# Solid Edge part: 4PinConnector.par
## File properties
Author: conerly
Template: Normal.par
Last saved by: jccrumbl
Revision: 55
Application: Solid Edge
Density: 1024.000 kg/m^3
Accuracy: 0.990
Material: ABS Plastic, high impact
Face Style: Red
Fill Style: ANSI34(Plastic)
Virtual Style: Red (Shiny)
Coef. of Thermal Exp: 9e-05
Thermal Conductivity: 0.2
Specific Heat: 0.0
Modulus of Elasticity: 1378951400.0
Poisson's Ratio: 0.4
Yield Stress: 31026406.5
Ultimate Stress: 0.0
Elongation: 0.0
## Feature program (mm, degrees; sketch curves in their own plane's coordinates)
sketch for "unnamed Protrusion 1" plane through (0, 0, 0) normal (0, 0, 1) x-axis (1, 0, 0)
  line (-37.2884, 10.9984) -> (-27.5384, 10.9984)
  line (-27.5384, 10.9984) -> (-27.5384, 20.7484)
  line (-27.5384, 20.7484) -> (-37.2884, 20.7484)
  line (-37.2884, 20.7484) -> (-37.2884, 10.9984)
  dimension (linear) = 27.5384
  dimension (linear) = 37.2884
extrude "unnamed Protrusion 1" add finite 25 along +normal
sketch for "ExtrudedProtrusion_3" plane through (-32.5384, 13.9984, 12.5) normal (0, -1, 0) x-axis (0, 0, 1)
  line (12.5, 4.75) -> (9.2, 4.75)
  line (9.2, 4.75) -> (9.2, 6.25)
  line (9.2, 6.25) -> (12.5, 4.75)
extrude "ExtrudedProtrusion_3" add finite 3.5 along -normal
sketch for "ExtrudedProtrusion_4" #1 plane through (-32.5384, 17.4984, 0) normal (0, 0, -1) x-axis (0, 1, 0)
  line (4.25, -3.75) -> (4.25, -5.75)
  line (4.25, -5.75) -> (2.25, -5.75)
  line (2.25, -3.75) -> (2.25, -5.75)
  line (4.25, -3.75) -> (2.25, -3.75)
sketch for "ExtrudedProtrusion_4" #2 plane through (-32.5384, 17.4984, 0) normal (0, 0, -1) x-axis (0, 1, 0)
  line (-5.5, -5.5) -> (-7.5, -5.5)
  line (-7.5, -5.5) -> (-7.5, -3.5)
  line (-5.5, -3.5) -> (-7.5, -3.5)
  line (-5.5, -3.5) -> (-5.5, -5.5)
sketch for "ExtrudedProtrusion_4" #3 plane through (-32.5384, 17.4984, 0) normal (0, 0, -1) x-axis (0, 1, 0)
  line (-7.5, 4) -> (-7.5, 6)
  line (-7.5, 6) -> (-5.5, 6)
  line (-5.5, 6) -> (-5.5, 4)
  line (-7.5, 4) -> (-5.5, 4)
sketch for "ExtrudedProtrusion_4" #4 plane through (-32.5384, 17.4984, 0) normal (0, 0, -1) x-axis (0, 1, 0)
  line (2.25, 6) -> (4.25, 6)
  line (4.25, 6) -> (4.25, 4)
  line (2.25, 4) -> (4.25, 4)
  line (2.25, 6) -> (2.25, 4)
  dimension (linear) = 2.25
extrude "ExtrudedProtrusion_4" add finite 12 along -normal
sketch for "ExtrudedProtrusion_5" #1 plane through (-32.2884, 17.4984, 12.5) normal (1, 0, 0) x-axis (0, -1, 0)
  line (6.5, 9.25) -> (8.75, 9.25)
  line (8.75, 9.25) -> (8.75, -1.4212)
  line (10.5, -2.3314) -> (8.75, -1.4212)
  line (10.5, -2.3314) -> (10.5, -2.9)
  line (10.5, -2.9) -> (7.5, -8.25)
  line (7.5, 6.75) -> (7.5, -8.25)
  line (6.5, 6.75) -> (7.5, 6.75)
  line (6.5, 9.25) -> (6.5, 6.75)
sketch for "ExtrudedProtrusion_5" #2 plane through (-32.2884, 17.4984, 12.5) normal (1, 0, 0) x-axis (0, -1, 0)
  line (-3.25, 9.25) -> (-5.5, 9.25)
  line (-5.5, 9.25) -> (-5.5, -1.4212)
  line (-7.25, -2.3314) -> (-5.5, -1.4212)
  line (-7.25, -2.3314) -> (-7.25, -2.9)
  line (-7.25, -2.9) -> (-4.25, -8.25)
  line (-4.25, 6.75) -> (-4.25, -8.25)
  line (-3.25, 6.75) -> (-4.25, 6.75)
  line (-3.25, 9.25) -> (-3.25, 6.75)
extrude "ExtrudedProtrusion_5" add finite 5 symmetric
sketch for "ExtrudedCutout_1" #1 plane through (-32.5384, 17.4984, 25) normal (0, 0, 1) x-axis (0, 1, 0)
  line (-1, -0.75) -> (2.5, -0.75)
  line (2.5, -0.75) -> (2.5, -4.25)
  line (2.5, -4.25) -> (-1, -4.25)
  line (-1, -4.25) -> (-1, -0.75)
sketch for "ExtrudedCutout_1" #2 plane through (-32.5384, 17.4984, 25) normal (0, 0, 1) x-axis (0, 1, 0)
  line (-1, 3.9418) -> (2.5, 3.9418)
  line (2.5, 3.9418) -> (2.5, 1.4418)
  line (2.5, 1.4418) -> (1.5, 0.4418)
  line (1.5, 0.4418) -> (0, 0.4418)
  line (0, 0.4418) -> (-1, 1.4418)
  line (-1, 1.4418) -> (-1, 3.9418)
sketch for "ExtrudedCutout_1" #3 plane through (-32.5384, 17.4984, 25) normal (0, 0, 1) x-axis (0, 1, 0)
  line (-5.5, 3.9418) -> (-2, 3.9418)
  line (-2, 3.9418) -> (-2, 0.4418)
  line (-2, 0.4418) -> (-5.5, 0.4418)
  line (-5.5, 0.4418) -> (-5.5, 3.9418)
sketch for "ExtrudedCutout_1" #4 plane through (-32.5384, 17.4984, 25) normal (0, 0, 1) x-axis (0, 1, 0)
  line (-5.5, -0.75) -> (-2, -0.75)
  line (-2, -0.75) -> (-2, -3.25)
  line (-2, -3.25) -> (-3, -4.25)
  line (-3, -4.25) -> (-4.5, -4.25)
  line (-4.5, -4.25) -> (-5.5, -3.25)
  line (-5.5, -3.25) -> (-5.5, -0.75)
  dimension (linear) = 2
  dimension (linear) = 1
  dimension (linear) = 2.5
  dimension (linear) = 2.5
  dimension (linear) = 2
extrude "ExtrudedCutout_1" cut finite 9 along -normal
sketch for "ExtrudedCutout_2" #1 plane through (-32.5384, 17.4984, 0) normal (0, 0, -1) x-axis (-1, 0, 0)
  line (3.9419, -2) -> (0.4419, -2)
  line (0.4419, -2) -> (0.4419, -5.5)
  line (0.4419, -5.5) -> (3.9419, -5.5)
  line (3.9419, -5.5) -> (3.9419, -2)
sketch for "ExtrudedCutout_2" #2 plane through (-32.5384, 17.4984, 0) normal (0, 0, -1) x-axis (-1, 0, 0)
  line (-0.75, -2) -> (-4.25, -2)
  line (-4.25, -2) -> (-4.25, -5.5)
  line (-4.25, -5.5) -> (-0.75, -5.5)
  line (-0.75, -5.5) -> (-0.75, -2)
sketch for "ExtrudedCutout_2" #3 plane through (-32.5384, 17.4984, 0) normal (0, 0, -1) x-axis (-1, 0, 0)
  line (-0.75, 2.5) -> (-4.25, 2.5)
  line (-4.25, 2.5) -> (-4.25, -1)
  line (-4.25, -1) -> (-0.75, -1)
  line (-0.75, -1) -> (-0.75, 2.5)
sketch for "ExtrudedCutout_2" #4 plane through (-32.5384, 17.4984, 0) normal (0, 0, -1) x-axis (-1, 0, 0)
  line (3.9419, 2.5) -> (0.4419, 2.5)
  line (0.4419, 2.5) -> (0.4419, -1)
  line (0.4419, -1) -> (3.9419, -1)
  line (3.9419, -1) -> (3.9419, 2.5)
extrude "ExtrudedCutout_2" cut finite 6 along -normal
sketch for "unnamed Cutout 1" #1 plane through (-34.7303, 13.7484, 6) normal (0, 0, -1) x-axis (1, 0, 0)
  circle centre (0, 0) radius 1
sketch for "unnamed Cutout 1" #2 plane through (-34.7303, 13.7484, 6) normal (0, 0, -1) x-axis (1, 0, 0)
  circle centre (4.6919, 0) radius 1
sketch for "unnamed Cutout 1" #3 plane through (-34.7303, 13.7484, 6) normal (0, 0, -1) x-axis (1, 0, 0)
  circle centre (4.6919, -4.5) radius 1
sketch for "unnamed Cutout 1" #4 plane through (-34.7303, 13.7484, 6) normal (0, 0, -1) x-axis (1, 0, 0)
  circle centre (-0.0581, -4.5) radius 1
extrude "unnamed Cutout 1" cut through along -normal
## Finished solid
Body 1: solid body, 96 faces, 246 edges, 158 vertices.
  Faces by surface: plane 92, cylinder 4
  Edges by curve: line 238, circle 8
Bounding box of the edges (mm): 12.250 x 17.750 x 25.000, from (-38.7884, 6.9984, 0) to (-26.5384, 24.7484, 25).
Cylindrical faces by radius (mm): R1 x4
Planar faces by outward normal: +x 15, +y 17, +z 11, -x 15, -y 17, -z 8, oblique 9
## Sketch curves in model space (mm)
circle centre (-30.0384, 18.2484, 6) radius 1
circle centre (-34.7884, 18.2484, 6) radius 1
circle centre (-30.0384, 13.7484, 6) radius 1
circle centre (-34.7303, 13.7484, 6) radius 1
line (-34.7303, 13.7484, 6) -> (-34.7303, 13.7484, -14.2417)
line (-30.0384, 13.7484, 6) -> (-30.0384, 13.7484, -14.2417)
line (-30.0384, 18.2484, 6) -> (-30.0384, 18.2484, -14.2417)
line (-34.7303, 18.2484, 6) -> (-34.7303, 18.2484, -14.2417)
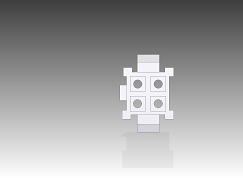
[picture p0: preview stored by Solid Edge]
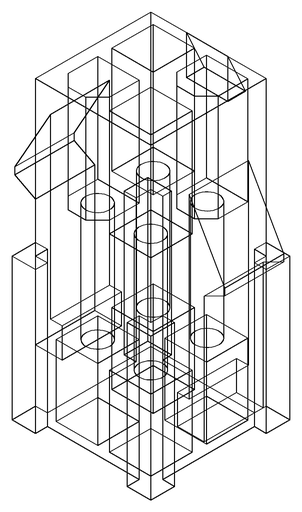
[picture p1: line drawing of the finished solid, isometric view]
